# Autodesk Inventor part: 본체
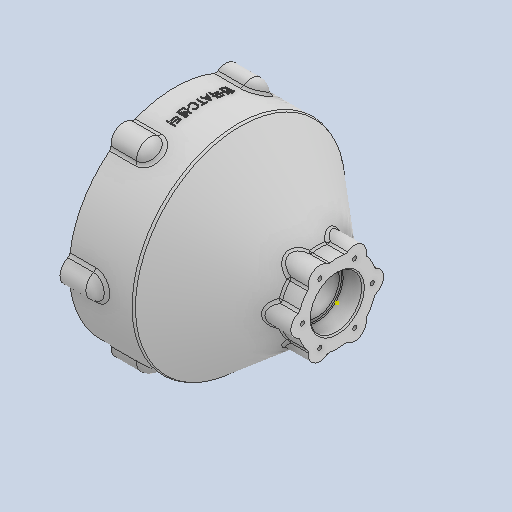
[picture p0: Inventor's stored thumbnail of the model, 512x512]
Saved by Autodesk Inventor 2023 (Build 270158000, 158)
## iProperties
Created: 2026-05
Part Number: 본체
Material: 일반
Document SubType Name: Modeling
Designer: home
Density: 1 g/cm^3
Appearance: 기본값
Mass: 736.757 g
Surface Area: 1183.24 cm^2
Volume: 736.757 cm^3
Author: home
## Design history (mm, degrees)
sketch "스케치1"
  geometry: L1 (-111.313, 0)-(0, 0); L2 (-126, 0)-(-126, 82); L3 (-126, 82)-(-76, 82); L4 (-76, 82)-(-14.625, 30.5); L5 (-14.625, 30.5)-(0, 30.5); L6 (0, 30.5)-(0, 0); L7 (-126, 73)-(-89, 73); L8 (-89, 73)-(-89, 68); L9 (-89, 68)-(-84, 68); L10 (-84, 68)-(-84, 56); L11 (-84, 56)-(-64, 56); L12 (-64, 56)-(-64, 40); L13 (-64, 40)-(-48, 40); L14 (-48, 40)-(-48, 37); L15 (-48, 37)-(-44, 37); L16 (-44, 37)-(-44, 20); L17 (-44, 20)-(-32, 20); L18 (-32, 20)-(-32, 17.5); L19 (-32, 17.5)-(-16, 17.5); L20 (-16, 17.5)-(-16, 20); L21 (-16, 20)-(0, 20); 2 further points
  constraints: 42 end point, 15 perpendicular, 5 point on line, 2 horizontal, 2 midpoint, 1 parallel, 1 vertical
  dimensions: "d0" = 126 distance from line of L1.end L2; "d1" = 164 diameter of point (-101, 82) L1; "d2" = 146 diameter of L7 L1; "d3" = 136 diameter of L9 L1; "d4" = 112 diameter of L11 L1; "d5" = 80 diameter of L13 L1; "d6" = 74 diameter of L15 L1; "d7" = 40 diameter of L17 L1; "d9" = 16 horizontal distance of L1.end point (-16, 18.75); "d10" = 37 distance of L7.start L7.end; "d11" = 94 distance from line of L2.start L18; "d12" = 12 distance of L16.end L17.end; "d16" = 50 distance of L2.end L3.end; "d17" = 126 horizontal distance of L1.end L2.end (derived); "d18" = 40 deg angle of L4 L3; "d19" = 61 diameter of L5 L1; "d20" = 40 diameter of L21 L1 (derived); "d21" = 5 distance of L8.end L9.end; "d22" = 25 distance between parallel lines of L12 L8; "d23" = 16 distance of L12.end L13.end; "d24" = 4 distance of L14.end L15.end (derived); "d25" = 35 diameter of L19 L1
revolve "회전1" sketch "스케치1" stored, may be unused: angle "d26" = 90 deg
sketch "스케치2"
  geometry: L1 (0, 0)-(79, 0); A1 r 79 centre (0, 0) between (78.367, -9.98) and (78.367, 9.98); A2 r 10 centre (79, 0) between (78.367, -9.98) and (78.367, 9.98); A3 r 79 centre (0, 0) between (78.367, -9.98) and (78.367, 9.98); 2 further points
  constraints: 8 point on circle, 4 coincident, 3 centre point, 2 end point, 1 horizontal
  dimensions: "d27" = 158 diameter of A1; "d28" = 20 diameter of A2
extrude "돌출1" join sketch "스케치2" distance "d29" = 20; taper "d30" = 0 deg
sketch "스케치4"
  geometry: L1 (-79, 0)-(0, 0)
  constraints: 2 end point, 1 horizontal
  dimensions: "d41" = 79 distance of L1.start L1.end
hole "구멍2" sketch "스케치4" at (0, 0) diameter "d42" = 4.917; stored, may be unused: countersink angle "d46" = 90 deg, drill point angle "d48" = 118 deg; dims "d43" = 12, "d44" = 4, "d45" = 2, "d47" = 14
sketch "스케치5"
  geometry: L1 (0, 0)-(62, 0)
  constraints: 2 end point, 1 horizontal
  dimensions: "d52" = 62 distance of L1.start L1.end
hole "구멍3" sketch "스케치5" at (62, 0) diameter "d53" = 3.242; stored, may be unused: countersink angle "d57" = 90 deg, drill point angle "d59" = 118 deg; dims "d54" = 8, "d55" = 4, "d56" = 2, "d58" = 10
sketch "스케치6"
  geometry: A1 r 27 centre (0, 0) between (-25.5, 8.874) and (-25.5, -8.874); A2 r 9 centre (-27, 0) between (-25.5, 8.874) and (-25.5, -8.874); A3 r 27 centre (0, 0) between (-25.5, 8.874) and (-25.5, -8.874); 1 further point
  constraints: 8 point on circle, 3 centre point, 2 coincident
  dimensions: "d63" = 54 diameter of A1; "d64" = 18 diameter of A2
extrude "돌출2" join sketch "스케치6" stored distance "d65" = 20; taper "d66" = 0 deg
sketch "스케치7"
  geometry: 1 further point
sketch "스케치8"
  geometry: L1 (27, 0)-(0, 0)
  constraints: 2 end point, 1 horizontal
  dimensions: "d70" = 27 distance of L1.start L1.end
hole "구멍4" sketch "스케치8" at (0, 0) diameter "d71" = 3.242; stored, may be unused: countersink angle "d75" = 90 deg, drill point angle "d77" = 118 deg; dims "d72" = 8, "d73" = 4, "d74" = 2, "d76" = 10
fillet "모깎기1" dims "d81" = 3
fillet "모깎기2" dims "d82" = 3
sketch "스케치9"
  geometry: L1 (106, 82)-(106, 81.424) reference; L2 (106, 89)-(106, 81.424) reference; L3 (106, 89)-(106, 89); L4 (106, 89)-(106, 79); L5 (96, 79)-(106, 79); A1 r 10 centre (106, 79) between (106, 89) and (96, 79); 4 further points
  constraints: 6 end point, 2 horizontal, 2 point on circle, 1 centre point, 1 point on line, 1 tangent, 1 vertical
  dimensions: "d83" = 10 distance of L2.start point (96, 89); "d84" = 10 radius of A1
revolve "회전2" sketch "스케치9" stored, may be unused: angle "d85" = 180 deg
fillet "모깎기3" dims "d89" = 3
chamfer "모따기1" distance "d90" = 1; stored, may be unused: second distance "d91" = 2, angle "d92" = 45 deg
fillet "모깎기4" dims "d93" = 0.6
chamfer "모따기2" distance "d94" = 1; stored, may be unused: second distance "d95" = 2, angle "d96" = 45 deg
fillet "모깎기5" dims "d97" = 3
fillet "모깎기6" dims "d98" = 1
chamfer "모따기3" distance "d99" = 1; stored, may be unused: second distance "d100" = 2, angle "d101" = 45 deg
node "작업 평면1"
sketch "스케치10"
  geometry: L1 (25, 30.625)-(25, -30.625) reference; 2 further points
  constraints: 1 horizontal alignment, 1 other
  dimensions: "d102" = 20 distance from line of L1 point (5, 0)
feature "엠보싱1" sketch "스케치10" dims "d0" = 126, "d1" = 164, "d2" = 146, "d3" = 136, "d4" = 112, "d5" = 80, "d6" = 74, "d7" = 40, "d9" = 16, "d10" = 37, "d11" = 94, "d12" = 12, "d16" = 50, "d17" = 126 (derived), "d18" = 40 deg, "d19" = 61, "d20" = 40 (derived), "d21" = 5, "d22" = 25, "d23" = 16, "d24" = 4 (derived), "d25" = 35, "d103" = 0.5, "d104" = 0
node "솔리드1"
pattern_circular "원형 패턴1" dims angle "d32" = 360 deg
pattern_circular "원형 패턴2" dims angle "d50" = 360 deg
pattern_circular "원형 패턴3" dims angle "d61" = 360 deg
pattern_circular "원형 패턴4" dims angle "d68" = 360 deg
pattern_circular "원형 패턴5" dims angle "d79" = 360 deg
pattern_circular "원형 패턴6" dims angle "d87" = 360 deg
feature "A9D066F2-1C7D-4E18-AEED-F7BC21143FA4" dims "d42" = 4.917, "d43" = 12, "d44" = 4, "d45" = 2, "d46" = 90 deg, "d47" = 14, "d48" = 118 deg
